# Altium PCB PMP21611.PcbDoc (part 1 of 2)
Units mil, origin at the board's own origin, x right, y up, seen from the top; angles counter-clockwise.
Board outline 4470 x 3145 mil, 4 copper layers (Top Layer, Signal Layer 1, Signal Layer 2, Bottom Layer), stack 60.6 mil thick; 95 components, 31 nets, 221 pads, 370 vias.
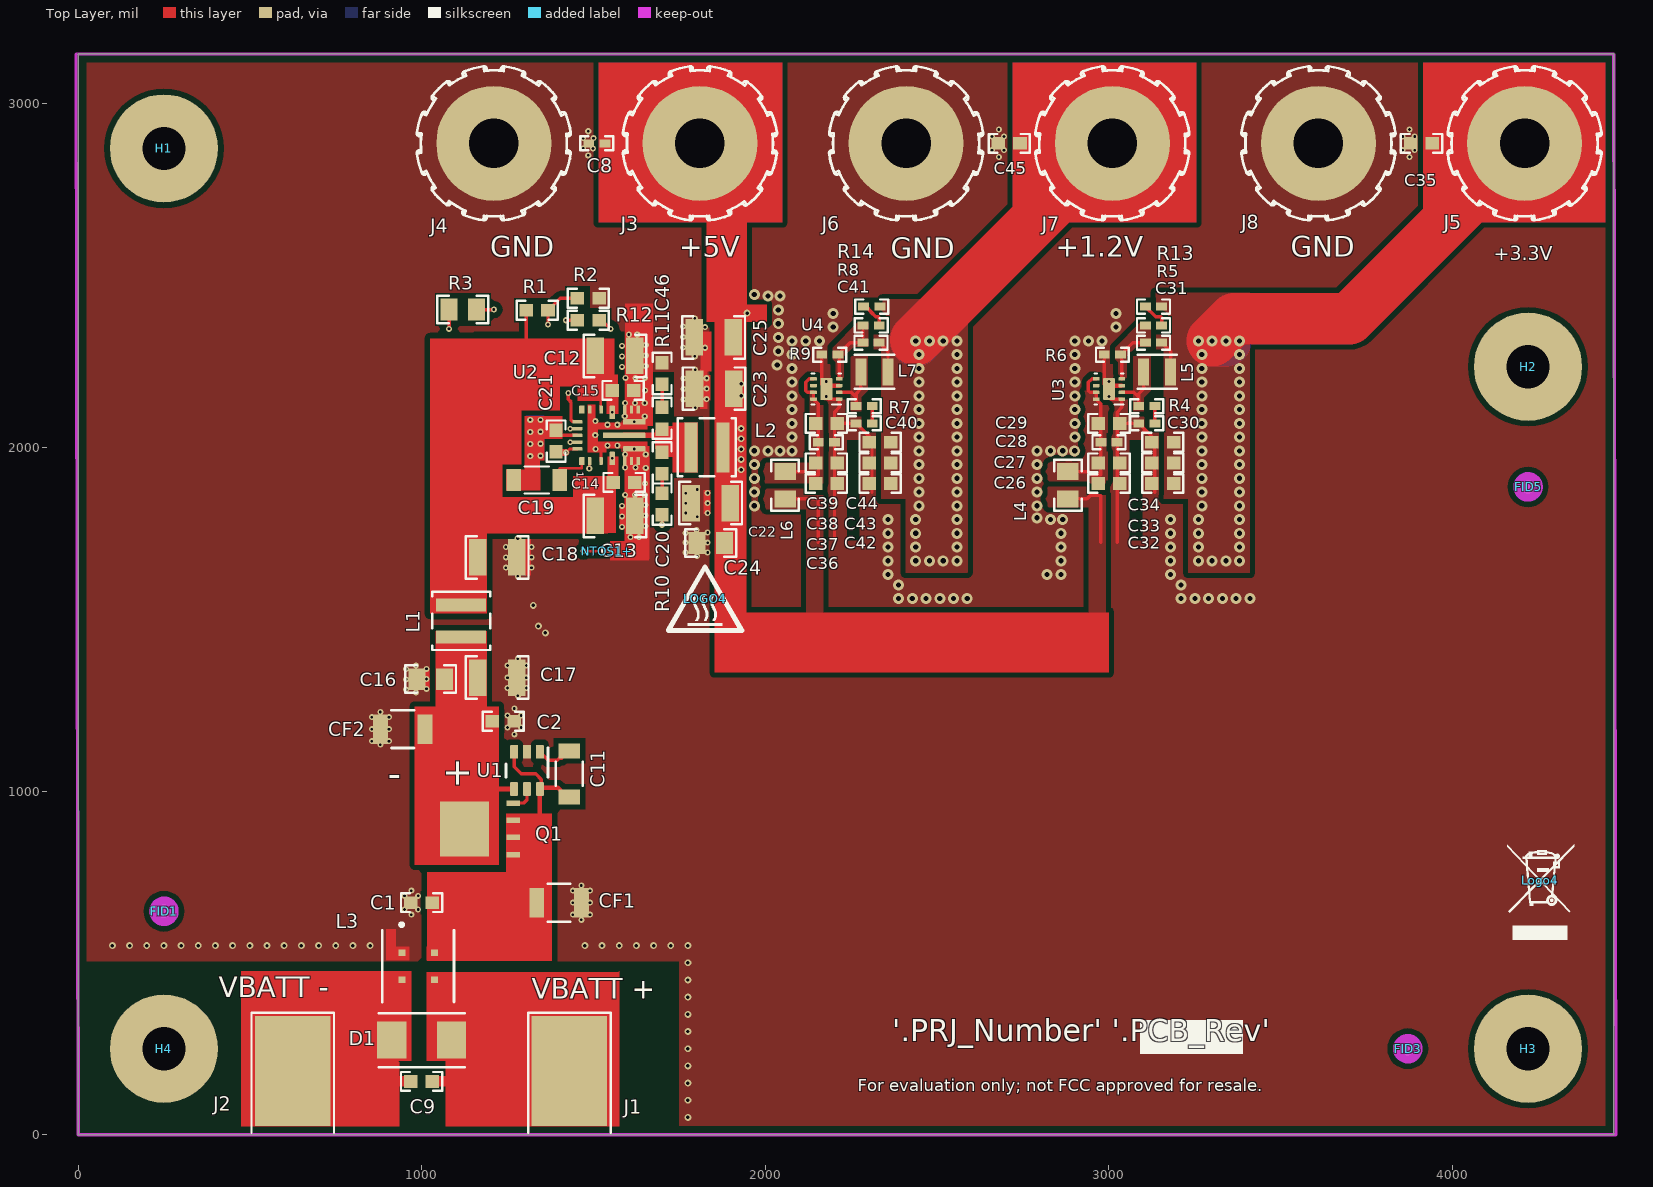
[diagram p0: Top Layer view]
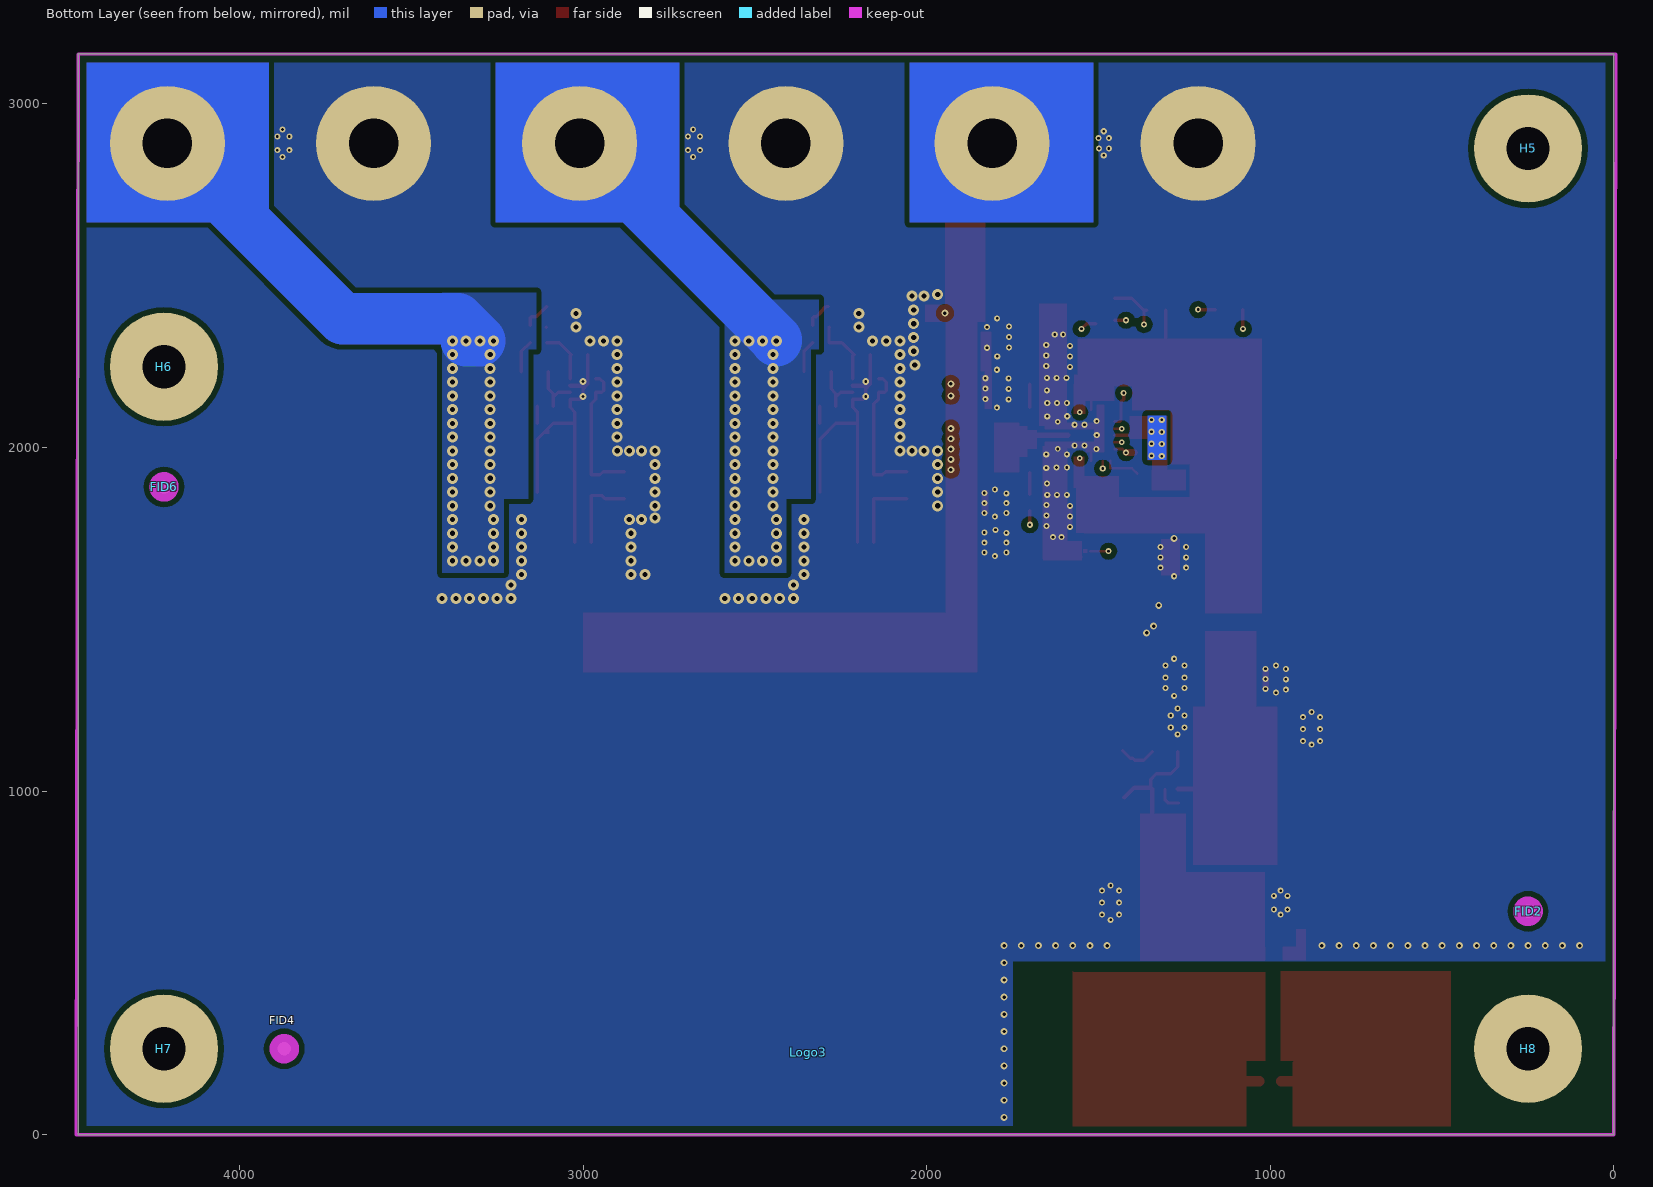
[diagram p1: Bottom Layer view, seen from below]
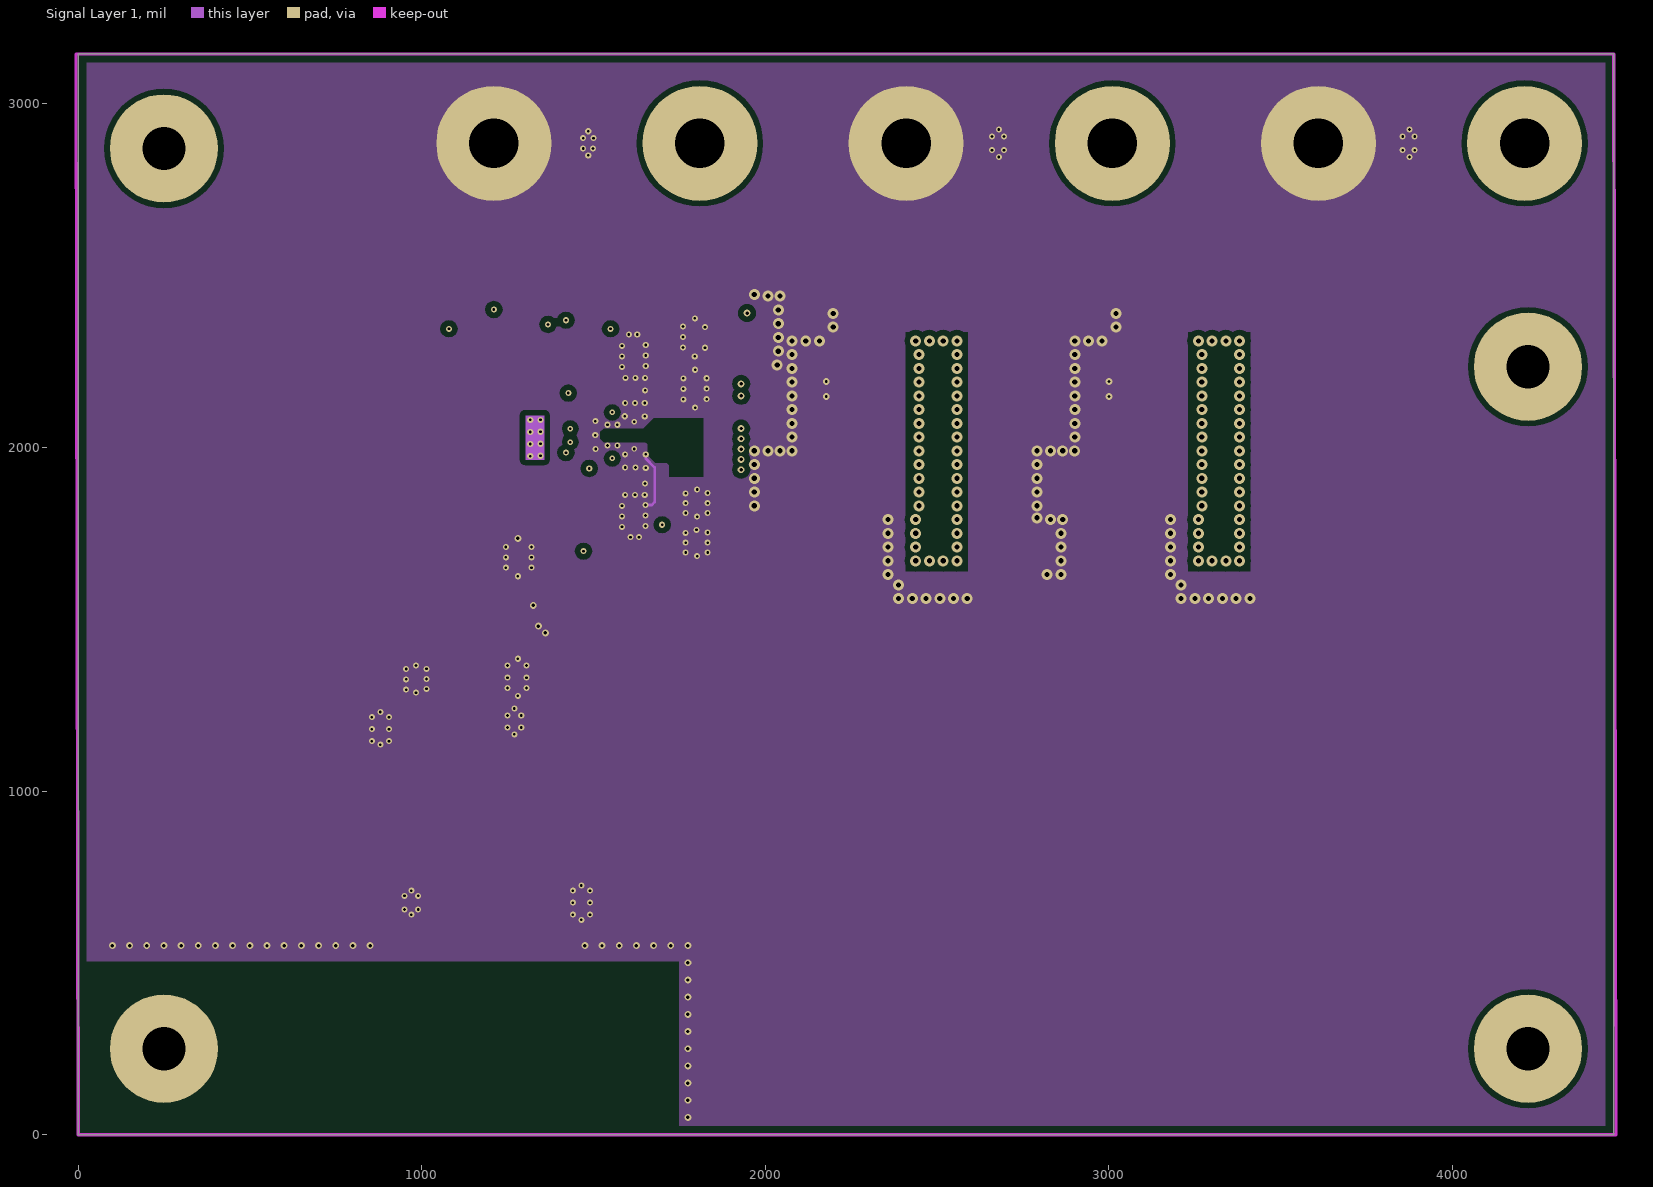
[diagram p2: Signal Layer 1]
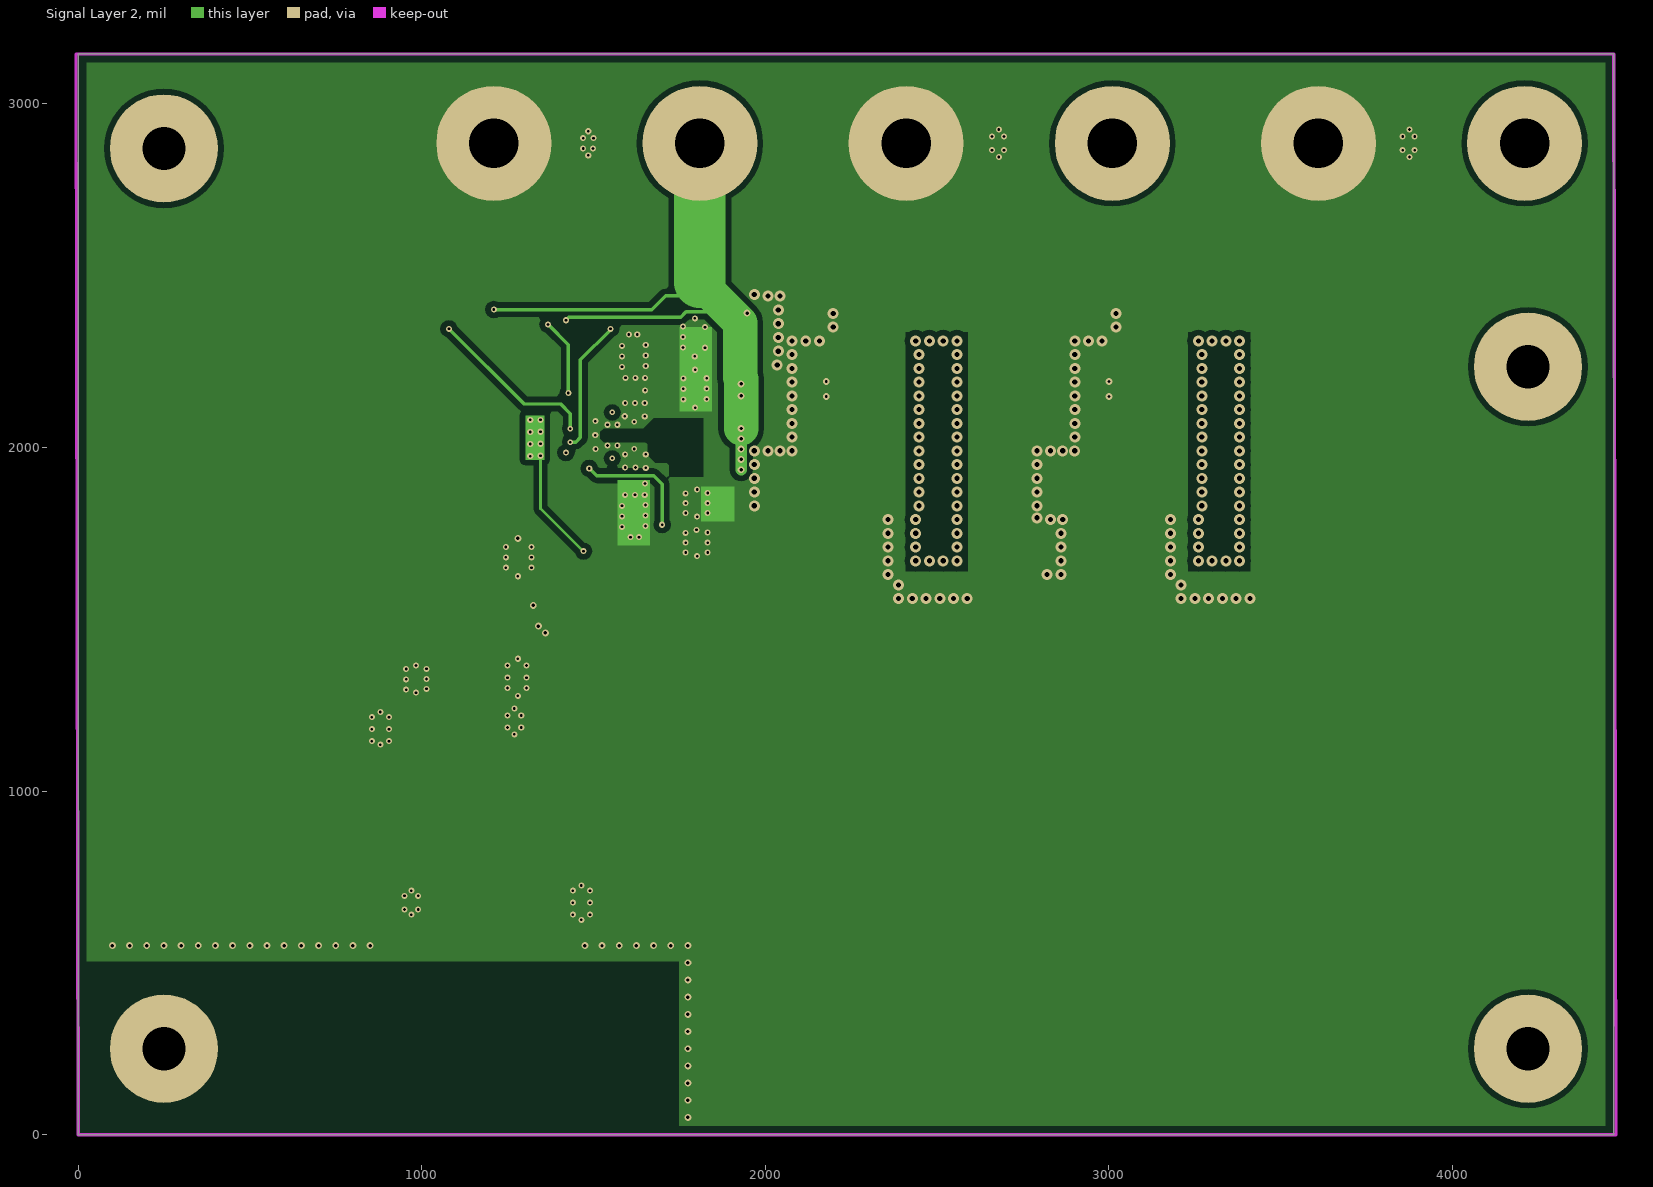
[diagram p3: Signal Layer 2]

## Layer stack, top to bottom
Top Solder: solder mask 0.4, Solder Resist, Dk 3.5
Top Layer: signal copper 1.4
Dielectric 1: prepreg 12, FR-4, Dk 4.2
Signal Layer 1: signal copper 1.4
Dielectric 2: core 31, FR-4, Dk 4.2
Signal Layer 2: signal copper 1.4
Dielectric 3: prepreg 12, FR-4, Dk 4.2
Bottom Layer: signal copper 1.4
Bottom Solder: solder mask 0.4, Solder Resist, Dk 3.5

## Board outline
0,0 0,3145 4470,3145 4470,0

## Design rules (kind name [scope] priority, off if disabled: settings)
AcuteAngle [All] p1: minimum=4.50000000000000E+0001 checktracksonly=FALSE
AssemblyTestPointUsage [All] p1: valid=2
BoardOutlineClearance BoardOutlineClearance_MountingHoles [OnCopper and InComponentClass('Mounting Holes')] p1: gap=40 ignorepadtopadclearanceinfootprint=FALSE
BoardOutlineClearance BoardOutlineClearance_Poly [OnCopper and IsPoly] p2: gap=25 ignorepadtopadclearanceinfootprint=FALSE
BoardOutlineClearance [OnCopper and Not InComponentClass('Logo') and not InComponentClass('FiducialMark') and not InRegion(1000,500,4000,800) and not InPoly] p3: gap=25 ignorepadtopadclearanceinfootprint=FALSE
Clearance Clearance_Keepouts [((IsTrack Or IsArc) And Not InPoly) And IsFree and IsKeepOut vs ((IsTrack Or IsArc) And Not InPoly) And IsFree and IsKeepOut] p1: gap=0 ignorepadtopadclearanceinfootprint=FALSE
Clearance Clearance_Poly [InPolygon] p2: gap=15.75 ignorepadtopadclearanceinfootprint=FALSE
Clearance [All] p3: gap=5 ignorepadtopadclearanceinfootprint=FALSE except(0: Arc-Hole Track-Hole SMDPad-Hole THPad-Hole Via-Hole Fill-Hole Poly-Hole Region-Hole Text-Hole)
ComponentClearance ComponentClearance_MountingHoles_FiducialMarks [InComponentClass('Mounting Holes') vs InComponentClass('FiducialMark')] p1: gap=50 collisioncheckmode=3 verticalgap=10 showdistances=FALSE
ComponentClearance ComponentClearance_Shunt [InComponentClass('Header') vs InComponentClass('Shunt')] p2: gap=0 collisioncheckmode=3 verticalgap=0 showdistances=FALSE
ComponentClearance ComponentClearance_Logo [InComponentClass('Logo')] p3: gap=50 collisioncheckmode=3 verticalgap=10 showdistances=FALSE
ComponentClearance ComponentClearance_ScrewToNut [(HasFootprint('NY PMS 440 0025 PH')) vs (HasFootprint('Keystone_1902C'))] p4: gap=5 collisioncheckmode=3 verticalgap=10 showdistances=FALSE
ComponentClearance ComponentClearance_MountingHoles [InComponentClass('Mounting Holes')] p5: gap=250 collisioncheckmode=3 verticalgap=100000 showdistances=FALSE
ComponentClearance ComponentClearance_SmallPassives [HasFootprint('0201*') or HasFootprint('0402*') or HasFootprint('0508') or HasFootprint('0603*') or HasFootprint('0612') or HasFootprint('0805*') or HasFootprint('0815*') or HasFootprint('0830*') or HasFootprint('1206*') or HasFootprint('1210*') or HasFootprint('1808*') or HasFootprint('1812*') or HasFootprint('1825*') or HasFootprint('2010*') or HasFootprint('2220*') or HasFootprint('2225*') or HasFootprint('2512*') or HasFootprint('2728*') or HasFootprint('3518*') vs HasFootprint('0201*') or HasFootprint('0402*') or HasFootprint('0508') or HasFootprint('0603*') or HasFootprint('0612') or HasFootprint('0805*') or HasFootprint('0815*') or HasFootprint('0830*') or HasFootprint('1206*') or HasFootprint('1210*') or HasFootprint('1808*') or HasFootprint('1812*') or HasFootprint('1825*') or HasFootprint('2010*') or HasFootprint('2220*') or HasFootprint('2225*') or HasFootprint('2512*') or HasFootprint('2728*') or HasFootprint('3518*')] p6: gap=14.96 collisioncheckmode=3 verticalgap=10 showdistances=FALSE
ComponentClearance ComponentClearance_THtoSMT [IsThruComponent vs IsSMTComponent] p7: gap=40 collisioncheckmode=3 verticalgap=30 showdistances=FALSE
ComponentClearance ComponentClearance_THtoTH [IsThruComponent vs IsThruComponent] p8: gap=30 collisioncheckmode=3 verticalgap=30 showdistances=FALSE
ComponentClearance [InComponent('No Component') vs InComponent('No Component')] p9: gap=10 collisioncheckmode=3 verticalgap=10 showdistances=FALSE
DiffPairsRouting [All] p1: maxlimit=100 minlimit=10 mostfreqgap=10 toplayer_minwidth=15 toplayer_maxwidth=15 toplayer_prefwidth=15 midlayer1_minwidth=15 midlayer1_maxwidth=15 midlayer1_prefwidth=15 midlayer2_minwidth=15 midlayer2_maxwidth=15 midlayer2_prefwidth=15 bottomlayer_minwidth=15 bottomlayer_maxwidth=15 bottomlayer_prefwidth=15 maxuncoupledlength=1000
FabricationTestPointUsage TestPointUsage [All] p1: valid=2 allowmultiple=FALSE
FabricationTestpoint Testpoint [All] p1: side=3 testpointundercomponent=TRUE minsize=40 maxsize=100 preferedsize=60 minholesize=0 maxholesize=40 preferedholesize=32 testpointgrid=1 allowsidetop=TRUE allowsidebottom=TRUE usegrid=TRUE gridtolerance=0.01
FanoutControl Fanout_LCC [IsLCC] p1: bgadir=Out bgaviamode=Centered fanoutstyle=Auto fanoutdirection=Alternating viagrid=1 // Fanout_LCC (Default Rule)
FanoutControl Fanout_BGA [IsBGA] p2: bgadir=Out bgaviamode=Centered fanoutstyle=Auto fanoutdirection=Alternating viagrid=1 // Fanout_BGA (Default Rule)
FanoutControl Fanout_Default [All] p4: bgadir=Out bgaviamode=Centered fanoutstyle=Auto fanoutdirection=Alternating viagrid=1 // Fanout_Default (Default Rule)
FanoutControl Fanout_Small [(CompPinCount < 5)] p5: bgadir=Out bgaviamode=Centered fanoutstyle=Auto fanoutdirection=OutThenIn viagrid=1 // Fanout_Small (Default Rule)
Height [All] p1: minheight=0 maxheight=2000 prefheight=500
HoleSize [All] p1: absolutevalues=TRUE maxlimit=251 minlimit=7.87 maxpercent=80.000 minpercent=20.000
MinimumAnnularRing MinimumAnnularRing_ThermalPadVias [IsVia and InAnyComponent] p1: minimumring=3.94
MinimumAnnularRing [All] p2: minimumring=3.94
MinimumSolderMaskSliver MinimumSolderMaskSliver_Logo [InComponentClass('Logo') vs InComponentClass('Logo')] p1: minsoldermaskwidth=0.7
MinimumSolderMaskSliver [All] p2: minsoldermaskwidth=3.94
PlaneConnect [All] p1: planeconnectstyle=Relief reliefexpansion=10 reliefentries=4 reliefconductorwidth=10 reliefairgap=10
PolygonConnect [All] p1: connectstyle=Direct reliefconductorwidth=10 reliefentries=4 polygonreliefangle="90 Angle" airgapwidth=10
RoutingVias ThermalPadVias [IsVia and InAnyComponent] p1: holewidth=7.87 width=19.68 viastyle="Through Hole" minholewidth=7.87 minwidth=15.75 maxholewidth=12.99 maxwidth=23.62
RoutingVias [All] p2: holewidth=16 width=34 viastyle="Through Hole" minholewidth=7.87 minwidth=15.75 maxholewidth=40 maxwidth=65
SilkToBoardRegionClearance [Not ((IsComment or IsDesignator) And (Hide <> 'False')) and not InRegion(1000,500,4000,800)] p1:
SilkToSilkClearance SilkToSilkClearance_Pb-FreeLogo [(HasFootprint('Pb-Free_Overlay_Medium') OR HasFootprint('Pb-Free_Overlay_Small')) vs (HasFootprint('Pb-Free_Overlay_Medium') OR HasFootprint('Pb-Free_Overlay_Small'))] p1: silktosilkclearance=0
SilkToSilkClearance [All] p2: silktosilkclearance=4
SilkToSolderMaskClearance SilkToComponentPadClearance [(IsPad or IsFill or IsRegion) and InAnycomponent] p1: minsilkscreentomaskgap=5 clearancetoexposedcopper=TRUE
SilkToSolderMaskClearance "Silk to Solder Mask Opening" [All] p2: minsilkscreentomaskgap=4 clearancetoexposedcopper=FALSE
SolderMaskExpansion [All] p1: expansion=1.97
Width [All] p1: maxlimit=200 minlimit=6 preferedwidth=10 checkconnectedcopper=TRUE
14 further rules are at their usual default settings.

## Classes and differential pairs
component class PMP21611_Dual: C26 C27 C28 C29 C30 C31 C32 C33 C34 C35 C36 C37 C38 C39 C40 C41 C42 C43 C44 C45 C48 C49 C50 C59 C60 J5 J6 J7 J8 L4 L5 L6 L7 R4 R5 R6 R7 R8 R9 R13 R14 U3 U4
component class PMP21611_Main: C1 C2 C8 C9 C11 C12 C13 C14 C15 C16 C17 C18 C19 C20 C21 C22 C23 C24 C25 C46 CF1 CF2 D1 J1 J2 J3 J4 L1 L2 L3 LOGO4 NTOS1+ Q1 R1 R2 R3 R10 R11 R12 R_FB1 U1 U2
component class PMP21611_Hardware: !PCB1 FID1 FID2 FID3 FID4 FID5 FID6 H1 H2 H3 H4 H5 H6 H7 H8 Logo3 Logo4

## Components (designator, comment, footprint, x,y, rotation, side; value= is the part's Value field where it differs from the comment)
C1 "CMP-0007135-4" 0603 1000,675 r180 top value=0.1uF
C2 "CMP-0007135-4" 0603 1237.69,1203 r0 top value=0.1uF
C8 "GCM155R71A104KA55D" 0402 1510,2885 r180 top value=0.1uF
C9 "06031C472KAT2A" 0603 1000,155 r180 top value=4700pF
C11 "C3216X7R1H225K160AB" 1206_180 1430,1050 r90 top value=2.2uF
C12 "GRM32ER7YA106KA12K" 1210_270 1562.72,2266.3 r0 top value=10uF
C13 "GRM32ER7YA106KA12K" 1210_270 1562.72,1800.75 r0 top value=10uF
C14 "C1608X7R1H473K080AA" 0603 1589.25,1898.19 r0 top value=0.047uF
C15 "C1608X7R1H473K080AA" 0603 1586.34,2165.91 r0 top value=0.047uF
C16 "C0805C104K5RACTU" 0805_HV 1026.19,1325.75 r180 top value=0.1uF
C17 "CL32B106KBJNNWE" 1210_270 1220,1330 r0 top value=10uF
C18 "CL32B106KBJNNWE" 1210_270 1220,1680 r0 top value=10uF
C19 "C3216X7R1H225K160AB" 1206_180 1335,1905 r180 top value=2.2uF
C20 "GCM188R71C474KA55D" 0603 1700,1955 r270 top locked value=0.47uF
C21 "GRM188R71H104KA93D" 0603 1391.46,2018.27 r270 top value=0.1uF
C22 "GRM32ER71A226ME20L" 1210_270 1841.16,1837.82 r180 top value=22uF
C23 "GRM32ER71A226ME20L" 1210_270 1851.14,2170.83 r180 top value=22uF
C24 "08055C473JAT2A" 0805_HV 1841.16,1721.8 r180 top value=0.047uF
C25 "GRM32ER71A226ME20L" 1210_270 1850,2320 r180 top value=22uF
C26 "GRM188Z71A106MA73D" 0603 3000.55,1895 r0 top value=10uF
C27 "GRM188Z71A106MA73D" 0603 3000.55,1955 r0 top value=10uF
C28 "GRM155R71A473KA01D" 0402 3000.55,2015 r0 top value=0.047uF
C29 "UMK107AB7105KA-T" 0603 3000.55,2070 r0 top value=1uF
C30 "GRM155R71H821KA01D" 0402 3110.55,2070 r180 top value=820pF
C31 "885012005055" 0402 3130,2305 r180 top value=10pF
C32 "GRM188Z71A106MA73D" 0603 3156.93,1895 r180 top value=10uF
C33 "GRM188Z71A106MA73D" 0603 3156.93,1955 r180 top value=10uF
C34 "UMK107AB7105KA-T" 0603 3156.93,2015 r180 top value=1uF
C35 "GCM188R71C474KA55D" 0603 3910,2885 r180 top value=0.47uF
C36 "GRM188Z71A106MA73D" 0603 2177.95,1895 r0 top value=10uF
C37 "GRM188Z71A106MA73D" 0603 2177.95,1955 r0 top value=10uF
C38 "GRM155R71A473KA01D" 0402 2177.95,2015 r0 top value=0.047uF
C39 "UMK107AB7105KA-T" 0603 2177.95,2070 r0 top value=1uF
C40 "GRM155R71H821KA01D" 0402 2287.95,2070 r180 top value=820pF
C41 "885012005043" 0402 2307.95,2305 r180 top value=33pF
C42 "GRM188Z71A106MA73D" 0603 2334.33,1895 r180 top value=10uF
C43 "GRM188Z71A106MA73D" 0603 2334.33,1955 r180 top value=10uF
C44 "UMK107AB7105KA-T" 0603 2334.33,2015 r180 top value=1uF
C45 "GCM188R71C474KA55D" 0603 2710,2885 r180 top value=0.47uF
C46 "C0603C821K5RACTU" 0603 1700,2215 r90 top value=820pF
CF1 "CMP-0009163-2" 1210_280 1400,675 r0 top value=4.7uF
CF2 "CMP-0009163-2" 1210_280 945,1180 r180 top value=4.7uF
D1 "CMP-0006046-2" SMB-Bi 1000,275 r180 top value=28V
FID1 "Fiducial" Fiducial10-20 250,650 r0 top
FID2 "Fiducial" Fiducial10-20 250,650 r180 bottom
FID3 "Fiducial" Fiducial10-20 3870,250 r0 top
FID4 "Fiducial" Fiducial10-20 3870,250 r180 bottom
FID5 "Fiducial" Fiducial10-20 4220,1885 r0 top
FID6 "Fiducial" Fiducial10-20 4220,1885 r180 bottom
H1 "NY PMS 440 0025 PH" "NY PMS 440 0025 PH" 250,2870 r0 top
H2 "NY PMS 440 0025 PH" "NY PMS 440 0025 PH" 4220,2235 r0 top
H3 "NY PMS 440 0025 PH" "NY PMS 440 0025 PH" 4220,250 r0 top
H4 "NY PMS 440 0025 PH" "NY PMS 440 0025 PH" 250,250 r0 top
H5 "1902B" Keystone_1902B 250,2870 r180 bottom
H6 "1902B" Keystone_1902B 4220,2235 r180 bottom
H7 "1902B" Keystone_1902B 4220,250 r180 bottom
H8 "1902B" Keystone_1902B 250,250 r180 bottom
J1 "VBATT +" 6091 1430,0 r90 top
J2 "VBATT -" 6092 625,0 r90 top
J3 "111-0702-001" Emerson_111-0702-001 1810,2885 r0 top
J4 "111-0703-001" Emerson_111-0703-001 1210,2885 r0 top
J5 "111-0702-001" Emerson_111-0702-001 4210,2885 r0 top
J6 "111-0703-001" Emerson_111-0703-001 2410,2885 r0 top
J7 "111-0702-001" Emerson_111-0702-001 3010,2885 r0 top
J8 "111-0703-001" Emerson_111-0703-001 3610,2885 r0 top
L1 "CMP-0060986-1" XAL4020 1115,1495 r90 top value=2.2uH
L2 "CMP-0060986-1" XAL4020 1830,2000 r0 top value=2.2uH
L3 "CMP-0076877-1" DLW5BT_TQ2 990,490 r0 top
L4 "7427920415" 0805_HV 2880.71,1890.16 r90 top value="600 ohm"
L5 "CMP-0058895-1" DFE252012C 3140.55,2220 r0 top value=1uH
L6 "7427920415" 0805_HV 2058.11,1890.16 r90 top value="600 ohm"
L7 "CMP-0058895-1" DFE252012C 2317.95,2220 r0 top value=1uH
Logo3 "FCC disclaimer" FCC_disclaimer 2345,240 r90 bottom
Logo4 "WEEE logo" WEEE_Minimum 4255,740 r0 top
LOGO4 "CAUTION HOT SURFACE" IEC_HotSurface_Small 1825,1560 r0 top
NTOS1+ "CMP-0078142-2" Net-Tie_10mil 1539,1698 r0 top net-tie
Q1 "CMP-0000747-1" PowerPAK_SO-8L 1156.69,890 r180 top value=40V
R1 "CRCW0603100KFKEA" 0603 1336.34,2399.17 r180 top value=100k
R2 "CRCW0603100KFKEA" 0603 1484.96,2434.17 r180 top value=100k
R3 "CRCW0805100KFKEA" 0805_HV 1119.8,2401.14 r0 top value=100k
R4 "CMP-0026565-2" 0402 3110.55,2120 r180 top value=7.50
R5 "CRCW0402806KFKED" 0402 3130,2355 r0 top value=806k
R6 "RC0402FR-07180KL" 0402 3010.55,2270 r0 top value=180k
R7 "CMP-0026565-2" 0402 2287.95,2120 r180 top value=7.50
R8 "RC0402FR-07180KL" 0402 2308.11,2355 r0 top value=180k
R9 "RC0402FR-07180KL" 0402 2187.95,2270 r0 top value=180k
R10 "RMCF0603ZT0R00" 0603 1700,1835 r90 top value=0
R11 "CRCW06037R50JNEA" 0603 1700,2085 r90 top value=7.5
R12 "RMCF0603ZT0R00" 0603 1485,2370 r180 top value=0
R13 "CRCW040247R5FKED" 0402 3130,2410 r0 top value=47.5
R14 "CRCW040247R5FKED" 0402 2310,2410 r0 top value=47.5
U1 "LM74700QDBVTQ1" DBV0006A_N 1306.69,1060 r270 top
U2 "LM53635LQRNLRQ1" RNL0022A 1545,2035 r90 top locked
U3 "TPS62067QDSGRQ1" DSG0008A 3000.55,2170 r180 top
U4 "TPS62067QDSGRQ1" DSG0008A 2177.95,2170 r180 top

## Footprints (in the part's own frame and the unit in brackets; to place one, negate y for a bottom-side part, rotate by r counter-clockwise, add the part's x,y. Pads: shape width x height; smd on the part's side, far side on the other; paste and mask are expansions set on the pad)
0402 [mm] "0402 from SM-752 data"
  rect 0.8x0.6 smd: 1(-0.6,0) 2(0.6,0)
  silkscreen extent -1.22,-0.52 1.22,0.52, body extent -0.55,-0.3 0.55,0.3, height 0.6
0603 [mm] "0603 from SM-752 data"
  rect 1x0.95 smd: 1(-0.8,0) 2(0.8,0)
  silkscreen extent -1.52,-0.69 1.52,0.69, body extent -0.87,-0.47 0.87,0.47, height 1
0805_HV [mil] "0805 with 30mil clearance between pads"
  rect 50x63 smd: 1(-40,0) 2(40,0)
  silkscreen extent -74,-40 74,40, body extent -43,-29 43,29, height 57
1206_180 [mm] "1206_180"
  rect 1.1x1.6 smd: 1(-1.7,0) 2(1.7,0)
  silkscreen extent -0.9,-1 0.9,1, body extent -1.75,-0.95 1.75,0.95, height 1.8
1210_270 [mm] "1210"
  rect 1.3x2.7 smd: 1(-1.45,0) 2(1.45,0)
  silkscreen extent -2.32,-1.57 2.32,1.57, body extent -1.7,-1.35 1.7,1.35, height 2.7
1210_280 [mm] "SMD, 2-Leads, Body 3.6x2.8mm, Height 2.8mm"
  rect 1.1x2.2 smd: 1(-1.65,0) 2(1.65,0)
  silkscreen extent -0.84,-1.4 0.84,1.4, body extent -1.8,-1.4 1.8,1.4, height 2.8
6091 [mil] "Keystone Insulated End Launch Banana Jack"
  rect 320x220 smd: 1(185,0)
  silkscreen extent 5,-120 355,120, body extent -666,-216 271,216, height 227
6092 [mil] "Keystone Insulated End Launch Banana Jack"
  rect 320x220 smd: 1(185,0)
  silkscreen extent 5,-120 355,120, body extent -666,-216 271,216, height 227
DBV0006A_N [mm] "SOT23, 6-Leads, Body 2.9x1.6mm, Pitch 0.95mm, Lead Span 2.8mm, IPC Medium Density"
  rrect17% 1x0.6 smd: 1(-1.375,0.95) 2(-1.375,0) 3(-1.375,-0.95) 4(1.375,-0.95) 5(1.375,0) 6(1.375,0.95)
  silkscreen extent -1.68,-1.55 0.5,1.55, body extent -1.42,-1.46 1.42,1.46, height 1.12
DFE252012C [mm] "Toko"
  rect 0.8x2 smd: 1(-1,0) 2(1,0)
  silkscreen extent -1.45,-1.25 1.45,1.25, body extent -1.35,-1.1 1.35,1.1, height 1.2
DLW5BT_TQ2 [mm] "SMD, 4-Leads, Body 5x5mm"
  rect 0.5x0.5 smd: 1(-1.2,1) 2(-1.2,-1) 3(1.2,-1) 4(1.2,1)
  Top Layer region: -2.35,-0.45 -0.65,-0.45 -0.65,-1.45 -1.65,-1.45 -1.65,-2.75 -2.35,-2.75
  Top Layer region: -2.35,0.45 -0.65,0.45 -0.65,1.45 -1.65,1.45 -1.65,2.75 -2.35,2.75
  Top Layer region: 2.35,-0.45 0.65,-0.45 0.65,-1.45 1.65,-1.45 1.65,-2.75 2.35,-2.75
  Top Layer region: 2.35,0.45 0.65,0.45 0.65,1.45 1.65,1.45 1.65,2.75 2.35,2.75
  silkscreen extent -2.65,-2.65 2.65,3.2, body extent -2.65,-2.65 2.65,2.65, height 2.51
DSG0008A [mm] "SON, 8-Leads, Body 2x2mm, Pitch 0.5mm, Thermal Pad 1.6x0.9mm, TI Recommended"
  rrect40% 0.5x0.25 smd: 1(-0.95,0.75) 2(-0.95,0.25) 3(-0.95,-0.25) 4(-0.95,-0.75) 5(0.95,-0.75) 6(0.95,-0.25) 7(0.95,0.25) 8(0.95,0.75)
  rrect14% 0.9x0.7 on Top Paste: 9(0,0.45) 9(0,-0.45)
  rrect11% 0.9x1.6 smd paste-0.45: 9(0,0)
  silkscreen extent -1.07,-1.15 1.07,1.15, body extent -1,-1 1,1, height 0.77
Emerson_111-0702-001 [mm] "Receptacle, 1x1 Position, Dia 10.74mm, Red, TH"
  round 8.5 hole 3.658: 1(0,0)
  silkscreen extent -5.69,-5.69 5.69,5.69, body extent -5.69,-5.69 5.69,5.69, height 26.47
Emerson_111-0703-001 [mm] "Receptacle, 1x1 Position, Dia 10.74mm, Black, TH"
  round 8.5 hole 3.658: 1(0,0)
  silkscreen extent -5.69,-5.69 5.69,5.69, body extent -5.69,-5.69 5.69,5.69, height 26.48
FCC_disclaimer [mil]
Fiducial10-20 [mm]
  round 1 smd mask+0.5: 1(0,0)
  Top Layer keep-out circle w1.178: c0,0 r0.5
IEC_HotSurface_Small [mil]
  silkscreen extent -107,-93 107,92
Keystone_1902B [mil] "Hex Standoff, 4-40 threaded, nylon"
  round 1 on Mech4: 0(0,0)
  body extent -145,-126 145,126, height 375
Net-Tie_10mil [mil] "10mil net tie, no solder mask opening, no solder paste"
  rect 10x10 smd paste-5 mask-5: 1(-10,0) 2(10,0)
  Top Layer region: -6,5 6,5 6,-5 -6,-5
"NY PMS 440 0025 PH" [mm] "4-40 nylon screw and mounting hole"
  round 8 hole 3.2: 1(0,0)
  body extent -3.3,-3.3 3.3,3.3, height 2.69
PowerPAK_SO-8L [mm] "based on Vishay recommended land pattern Document 63818 Feb 7, 2012"
  rect 1x0.41 smd: 1(-2.805,1.905) 2(-2.805,0.635) 3(-2.805,-0.635) 4(-2.805,-1.905)
  rect 3.63x4.061 smd: 5(0.805,0)
  Top Layer region: 2.615,-2.5 3.125,-2.5 3.125,2.5 2.615,2.5
  Top Layer region: -0.298,2.03 0.298,2.03 0.298,2.64 -0.298,2.64
  Top Layer region: -0.298,-2.64 0.298,-2.64 0.298,-2.03 -0.298,-2.03
  body extent -3.07,-2.57 3.08,2.57, height 1.21
RNL0022A [mm] "VQFN-HR-22"
  rrect25% 0.6x0.4 smd: 1(-1.9,2) 17(1.9,2)
  rrect40% 0.6x0.25 smd: 2(-1.9,1.425) 3(-1.9,0.575) 5(-1.9,-1.175) 6(-1.9,-1.675) 7(-1.9,-2.175) 11(1.9,-2.175) 12(1.9,-1.675) 13(1.9,-1.175) 15(1.9,0.575) 16(1.9,1.425)
  rrect25% 1x0.4 smd paste-0.25: 4(-1.7,-0.25) 14(1.7,-0.25)
  rrect25% 0.4x0.4 on Top Paste: 4A(-2,-0.25) 4B(-1.4,-0.25) 14A(1.4,-0.25) 14B(2,-0.25)
  rrect25% 0.4x1.65 smd paste-0.25: 8(-1,-1.875) 10(1,-1.875)
  rrect25% 0.4x0.66 on Top Paste: 8A(-1,-1.445) 8B(-1,-2.305) 10A(1,-1.445) 10B(1,-2.305)
  rrect25% 0.4x3.15 smd paste-0.25: 9(0,-1.125)
  rrect25% 0.4x0.63 on Top Paste: 9A(0,0.12) 9B(0,-0.71) 9C(0,-1.54) 9D(0,-2.37)
  rrect40% 0.25x0.75 smd: 18(1,2.325) 19(0.5,2.325) 20(0,2.325) 21(-0.5,2.325) 22(-1,2.325)
  body extent -2,-2.5 2,2.5, height 0.9
SMB-Bi [mil] "Molded Diode, 2-Leads, Body 5.4x3.6mm, IPC Medium Density, based on OnSemi component dimensions"
  rect 85x107.99 smd: 1(-87.01,0) 2(87.01,0)
  silkscreen extent -125,-79 125,79, body extent -104,-73 104,73, height 89
WEEE_Minimum [mil] "WEEElie bin"
  silkscreen extent -95,-172 99,104
XAL4020 [mil] "Coilcraft XAL4020 7/18/12"
  rect 38x146 smd: 1(-46.5,0) 2(46.5,0)
  silkscreen extent -84,-84 84,84, body extent -84,-84 84,84, height 83

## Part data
C1 C2: "CAP, CERM, 0.1 uF, 16 V, +/- 10%, X7R, AEC-Q200 Grade 1, 0603", Cap_Case=0603, Manufacturer=MuRata, PartNumber=GCM188R71C104KA37J, Supplier Part Number 1=490-8015-1-ND, TempCo=X7R, Tolerance_%=10%, Value1=Unknown, Value2=16V, ValueDisplayed=0.1uF
C8: library part CMP-0006350-2, "CAP, CERM, 0.1 uF, 10 V, +/- 10%, X7R, AEC-Q200 Grade 1, 0402", Cap_Case=0402, Manufacturer=MuRata, Supplier Part Number 1=81-GCM155R71A104K5D, TempCo=X7R, Tolerance_%=10%, Value1=Unknown, Value2=10V, ValueDisplayed=0.1uF
C9: library part CMP-0006746-5, "CAP, CERM, 4700 pF, 100 V, +/- 10%, X7R, 0603", Cap_Case=0603, Manufacturer=AVX, Supplier Part Number 1=478-1203-1-ND, TempCo=X7R, Tolerance_%=10%, Value1="0.136 ohm", Value2=100V, ValueDisplayed=4700pF
C11 C19: library part CMP-0008698-2, "CAP, CERM, 2.2 uF, 50 V, +/- 10%, X7R, 1206", Cap_Case=1206_180, Manufacturer=TDK, Supplier Part Number 1=445-7697-1-ND, TempCo=X7R, Tolerance_%=10%, Value1="0.005887 ohm", Value2=50V, ValueDisplayed=2.2uF
C12 C13: library part CMP-0081639-1, "CAP, CERM, 10 µF, 35 V,+/- 10%, X7R, 1210", Cap_Case=1210, Manufacturer=MuRata, Supplier Part Number 1=GRM32ER7YA106KA12K-ND, TempCo=X7R, Tolerance_%=10%, Value1="0.001 ohm", Value2=35V, ValueDisplayed=10µF
C14 C15: library part CMP-0007049-4, "CAP, CERM, 0.047 uF, 50 V, +/- 10%, X7R, 0603", Cap_Case=0603, Manufacturer=TDK, Supplier Part Number 1=445-1313-1-ND, TempCo=X7R, Tolerance_%=10%, Value1="0.049007 ohm", Value2=50V, ValueDisplayed=0.047uF
C16: library part CMP-0007726-2, "CAP, CERM, 0.1 uF, 50 V, +/- 10%, X7R, 0805", Cap_Case=0805, Manufacturer=Kemet, Supplier Part Number 1=399-1170-1-ND, TempCo=X7R, Tolerance_%=10%, Value1="0.064 ohm", Value2=50V, ValueDisplayed=0.1uF
C17 C18: library part CMP-0079201-1, "CAP, CERM, 10 µF, 50 V,+/- 10%, X7R, 1210", Cap_Case=1210, Manufacturer="Samsung Electro-Mechanics", Supplier Part Number 1=1276-3388-1-ND, TempCo=X7R, Tolerance_%=10%, Value1="0.005 ohm", Value2=50V, ValueDisplayed=10µF
C20 C35 C45: library part CMP-0007138-4, "CAP, CERM, 0.47 uF, 16 V, +/- 10%, X7R, AEC-Q200 Grade 1, 0603", Cap_Case=0603, Manufacturer=MuRata, Supplier Part Number 1=490-4775-1-ND, TempCo=X7R, Tolerance_%=10%, Value1=Unknown, Value2=16V, ValueDisplayed=0.47uF
C21: library part CMP-0007434-4, "CAP, CERM, 0.1 uF, 50 V, +/- 10%, X7R, 0603", Cap_Case=0603, Manufacturer=MuRata, Supplier Part Number 1=490-1519-1-ND, TempCo=X7R, Tolerance_%=10%, Value1=Unknown, Value2=50V, ValueDisplayed=0.1uF
C22 C23 C25: library part CMP-0009219-2, "CAP, CERM, 22 uF, 10 V, +/- 10%, X7R, 1210", Cap_Case=1210, Manufacturer=MuRata, Supplier Part Number 1=490-11653-1-ND, TempCo=X7R, Tolerance_%=10%, Value1="0.002 ohm", Value2=10V, ValueDisplayed=22uF
C24: library part CMP-0007658-2, "CAP, CERM, 0.047 uF, 50 V, +/- 5%, X7R, 0805", Cap_Case=0805, Manufacturer=AVX, Supplier Part Number 1=478-3771-1-ND, TempCo=X7R, Tolerance_%=5%, Value1="0.035 ohm", Value2=50V, ValueDisplayed=0.047uF
C26 C27 C32 C33 C36 C37 C42 C43: library part CMP-0007497-5, "CAP, CERM, 10 uF, 10 V, +/- 20%, X7R, 0603", Cap_Case=0603, Manufacturer=MuRata, Supplier Part Number 1=81-GRM188Z71A106MA3D, TempCo=X7R, Tolerance_%=20%, Value1=Unknown, Value2=10V, ValueDisplayed=10uF
C28 C38: library part CMP-0006634-2, "CAP, CERM, 0.047 uF, 10 V, +/- 10%, X7R, 0402", Cap_Case=0402, Manufacturer=MuRata, Supplier Part Number 1=490-1316-1-ND, TempCo=X7R, Tolerance_%=10%, Value1=Unknown, Value2=10V, ValueDisplayed=0.047uF
C29 C34 C39 C44: library part CMP-0007508-5, "CAP, CERM, 1 uF, 50 V, +/- 10%, X7R, 0603", Cap_Case=0603, Manufacturer="Taiyo Yuden", Supplier Part Number 1=587-3247-1-ND, TempCo=X7R, Tolerance_%=10%, Value1=Unknown, Value2=50V, ValueDisplayed=1uF
C30 C40: library part CMP-0006697-2, "CAP, CERM, 820 pF, 50 V, +/- 10%, X7R, 0402", Cap_Case=0402, Manufacturer=MuRata, Supplier Part Number 1=490-3250-1-ND, TempCo=X7R, Tolerance_%=10%, Value1=Unknown, Value2=50V, ValueDisplayed=820pF
C31: library part CMP-0006215-2, "CAP, CERM, 10 pF, 50 V, +/- 5%, C0G/NP0, 0402", Cap_Case=0402, Manufacturer="Wurth Elektronik", Supplier Part Number 1=732-7469-1-ND, TempCo=C0G/NP0, Tolerance_%=5%, Value1=Unknown, Value2=50V, ValueDisplayed=10pF
C41: library part CMP-0006213-2, "CAP, CERM, 33 pF, 25 V, +/- 5%, C0G/NP0, 0402", Cap_Case=0402, Manufacturer="Wurth Elektronik", Supplier Part Number 1=710-885012005043, TempCo=C0G/NP0, Tolerance_%=5%, Value1=Unknown, Value2=25V, ValueDisplayed=33pF
C46: library part CMP-0006972-5, "CAP, CERM, 820 pF, 50 V, +/- 10%, X7R, 0603", Cap_Case=0603, Manufacturer=Kemet, Supplier Part Number 1=399-1078-1-ND, TempCo=X7R, Tolerance_%=10%, Value1=Unknown, Value2=50V, ValueDisplayed=820pF
CF1 CF2: "CAP, CERM, 4.7 uF, 50 V, +/- 20%, X7R, AEC-Q200 Grade 1, 1210", Cap_Case=1210, Manufacturer=TDK, PartNumber=CGA6P3X7R1H475M250AB, Supplier Part Number 1=445-13030-1-ND, TempCo=X7R, Tolerance_%=20%, Value1=Unknown, Value2=50V, ValueDisplayed=4.7uF
D1: "Diode, TVS, Bi, 28 V, 45.4 Vc, SMB", Manufacturer="Diodes Inc.", PartNumber=SMBJ28CA-13-F, Power_W=5W, Supplier Part Number 1=SMBJ28CA-FDICT-ND
FID1 FID2 FID3 FID4 FID5 FID6: "Fiducial mark.  There is nothing to buy or mount.", Manufacturer=N/A
H1 H2 H3 H4: library part CMP-0003617-1, "Machine Screw, Round, #4-40 x 1/4, Nylon, Philips panhead", Manufacturer="B&F Fastener Supply", Supplier Part Number 1=H542-ND
H5 H6 H7 H8: library part CMP-0003658-1, Manufacturer=Keystone, Supplier Part Number 1=36-1902B-ND
J1: library part CMP-0055167-2, "Standard Banana Jack, Insulated, Red", Manufacturer=Keystone, PartNumber=6091, Supplier Part Number 1=36-6091-ND
J2: library part CMP-0055168-2, "Standard Banana Jack, Insulated, Black", Manufacturer=Keystone, PartNumber=6092, Supplier Part Number 1=36-6092-ND
J3 J5 J7: library part CMP-0075036-1, "Binding Post, Red, TH", Manufacturer="Cinch Connectivity", Supplier Part Number 1=J10125-ND
J4 J6 J8: library part CMP-0075035-1, "Binding Post, Black, TH", Manufacturer="Cinch Connectivity", Supplier Part Number 1=J10126-ND
L1 L2: "Inductor, Shielded, Composite, 2.2 uH, 5.5 A, 0.04 ohm, SMD", Manufacturer=Coilcraft, PartNumber=XAL4020-222MEB, Value1="0.04 ohm", Value2=5.5A, ValueDisplayed=2.2uH
L3: "Coupled inductor, 2.5 A, 0.034 ohm, SMD", Manufacturer=MuRata, PartNumber=DLW5BTM102TQ2K, Supplier Part Number 1=490-9291-1-ND
L4 L6: library part CMP-0003086-1, "Ferrite Bead, 600 ohm @ 100 MHz, 0.5 A, 0805", Manufacturer="Wurth Elektronik", Supplier Part Number 1=732-1605-1-ND, Value1="0.3 ohm", Value2=0.5A, ValueDisplayed="600 ohm"
L5 L7: "Inductor, Shielded, Ferrite, 1 uH, 3 A, 0.045 ohm, SMD", Manufacturer="MuRata Toko", PartNumber=1239AS-H-1R0M{}P2, Value1="0.045 ohm", Value2=3A, ValueDisplayed=1uH
Logo3: library part FCC_disclaimer, "FCC_disclaimer"
Logo4: library part CMP-0074769-1
LOGO4: library part IEC_HotSurface, "IEC 61010-1 Hot Surface Warning"
NTOS1+: "Single point connection between nets.", Manufacturer=N/A
Q1: "MOSFET, N-CH, 40 V, 75 A, PowerPAK_SO-8L", Alternate Manufacturer=None, Manufacturer=Vishay-Siliconix, PartNumber=SQJ422EP-T1-GE3, Supplier Part Number 1=SQJ422EP-T1-GE3-ND, Value1=0.004, Value2="67 nC"
R1 R2: library part CMP-0021990-4, "RES, 100 k, 1%, 0.1 W, AEC-Q200 Grade 0, 0603", Manufacturer=Vishay-Dale, Power_W=100mW, Supplier Part Number 1=541-100KHCT-ND, TempCo="100 ppm/C", Tolerance_%=1%, Value2=0.1W, Value_Code=100k
R3: library part CMP-0020834-3, "RES, 100 k, 1%, 0.125 W, AEC-Q200 Grade 0, 0805", Manufacturer=Vishay-Dale, Power_W=125mW, Supplier Part Number 1=541-100KCCT-ND, TempCo="100 ppm/C", Tolerance_%=1%, Value2=0.125W, Value_Code=100k
R4 R7: "RES, 7.50, 1%, 0.063 W, AEC-Q200 Grade 0, 0402", Manufacturer=Vishay-Dale, PartNumber=CRCW04027R50FKED, Power_W=63mW, Supplier Part Number 1=541-7.50LLCT-ND, TempCo="100 ppm/C", Tolerance_%=1%, Value2=0.063W, Value_Code=7R50, ValueDisplayed=7.50
R5: library part CMP-0026568-2, "RES, 806 k, 1%, 0.063 W, AEC-Q200 Grade 0, 0402", Manufacturer=Vishay-Dale, Power_W=63mW, Supplier Part Number 1=541-806KLCT-ND, TempCo="100 ppm/C", Tolerance_%=1%, Value2=0.063W, Value_Code=806k
R6 R8 R9: library part CMP-0026723-1, "RES, 180 k, 1%, 0.063 W, 0402", Manufacturer="Yageo America", Power_W=63mW, Supplier Part Number 1=311-180KLRCT-ND, TempCo="100 ppm/C", Tolerance_%=1%, Value2=0.063W, Value_Code=180k
R10 R12: library part CMP-0023343-3, "RES, 0, 1%, 0.1 W, AEC-Q200 Grade 0, 0603", Manufacturer="Stackpole Electronics Inc", Power_W=100mW, Supplier Part Number 1=RMCF0603ZT0R00CT-ND, TempCo=ppm/C, Tolerance_%=1%, Value2=0.1W, Value_Code=0
R11: library part CMP-0025857-4, "RES, 7.5, 5%, 0.1 W, AEC-Q200 Grade 0, 0603", Manufacturer=Vishay-Dale, Power_W=100mW, Supplier Part Number 1=541-7.5GCT-ND, TempCo="200 ppm/C", Tolerance_%=5%, Value2=0.1W, Value_Code=7R50, ValueDisplayed=7.5
R13 R14: library part CMP-0026396-2, "RES, 47.5, 1%, 0.063 W, AEC-Q200 Grade 0, 0402", Manufacturer=Vishay-Dale, Power_W=63mW, Supplier Part Number 1=541-47.5LCT-ND, TempCo="100 ppm/C", Tolerance_%=1%, Value2=0.063W, Value_Code=47R5, ValueDisplayed=47.5
U1: library part CMP-0079180-1, "Low Iq Always ON Smart Diode Controller, DBV0006A (SOT-23-6)", Alternate Manufacturer="Texas Instruments", Alternate PartNumber=LM74700QDBVRQ1
U2: library part CMP-0076355-4, "3.5A, 36 V Synchronous, 2.1MHz, Automotive Step Down DC-DC Converter, RNL0022A (VQFN-HR-22)", Alternate Manufacturer="Texas Instruments", Alternate PartNumber=LM53635LQRNLTQ1, Operating Temprature Range="-40 to 150 C", Rating=Automotive
U3 U4: library part CMP-0081411-1, "3MHz, 2A Automotive Step-Down Converter in 2x2 SON Package, DSG0008A (WSON-8)", Alternate Manufacturer="Texas Instruments", Operating Temprature Range="-40 to 125 C", Rating=Automotive

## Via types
v1: diameter 32, hole 15, Top Layer to Bottom Layer, tented both sides, 156 vias
v2: diameter 17.72, hole 7.87, Top Layer to Bottom Layer, tented both sides, 150 vias
v3: diameter 20, hole 10, Top Layer to Bottom Layer, tented both sides, 45 vias
v4: diameter 17.72, hole 7.87, Top Layer to Bottom Layer, 9 vias
v5: diameter 15.75, hole 7.87, Top Layer to Bottom Layer, 5 vias
v6: diameter 19.68, hole 7.87, Top Layer to Bottom Layer, 4 vias
v7: diameter 15.75, hole 7.87, Top Layer to Bottom Layer, tented both sides, 1 vias

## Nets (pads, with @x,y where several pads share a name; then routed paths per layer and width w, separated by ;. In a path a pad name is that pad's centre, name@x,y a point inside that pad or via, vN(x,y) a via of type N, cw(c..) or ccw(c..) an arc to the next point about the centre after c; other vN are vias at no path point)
+1.2V: C41.1 C42.1 C43.1 C44.1 C45.1 J7.1 L7.2 R14.2 | length 1988.3
  Top Layer w10: C41.1@2331.57,2305.31 2357.32,2279.57 L7.2@2357.32,2220
  Top Layer w20: C45.1@2733.62,2885 J7.1@3005,2885
  Top Layer w150: v1@2437.95,2312.95 J7.1@3010,2885
  Bottom Layer w150: v1(2437.95,2310) 2437.95,2312.95 J7.1@3010,2885
  other v1: 2437.95,1670 2477.95,1670 2517.95,1670 2557.95,1670 2437.95,1710 2557.95,1710 2437.95,1750 2557.95,1750 2437.95,1790 2557.95,1790 2447.95,1830 2557.95,1830 2447.95,1870 2557.95,1870 2447.95,1910 2557.95,1910 2447.95,1950 2557.95,1950 2447.95,1990 2557.95,1990 2447.95,2030 2557.95,2030 2447.95,2070 2557.95,2070 2447.95,2110 2557.95,2110 2447.95,2150 2557.95,2150 2447.95,2190 2557.95,2190 2447.95,2230 2557.95,2230 2447.95,2270 2557.95,2270 2477.95,2310 2517.95,2310 2557.95,2310
+3.3V: C31.1 C32.1 C33.1 C34.1 C35.1 J5.1 L5.2 R13.2 | length 2708
  Top Layer w10: C31.1@3153.62,2305 3154.49,2305 3179.92,2279.57 L5.2@3179.92,2220
  Top Layer w20: C35.1@3933.62,2885 J5.1@4210,2885
  Top Layer w150: v1(3300.55,2310) 3365.55,2375 3700,2375 J5.1@4210,2885
  Bottom Layer w150: v1(3340.55,2310) v1(3300.55,2310) 3365.55,2375 3700,2375 J5.1@4210,2885
  other v1: 3260.55,1670 3300.55,1670 3340.55,1670 3380.55,1670 3260.55,1710 3380.55,1710 3260.55,1750 3380.55,1750 3260.55,1790 3380.55,1790 3270.55,1830 3380.55,1830 3270.55,1870 3380.55,1870 3270.55,1910 3380.55,1910 3270.55,1950 3380.55,1950 3270.55,1990 3380.55,1990 3270.55,2030 3380.55,2030 3270.55,2070 3380.55,2070 3270.55,2110 3380.55,2110 3270.55,2150 3380.55,2150 3270.55,2190 3380.55,2190 3270.55,2230 3380.55,2230 3270.55,2270 3380.55,2270 3260.55,2310 3380.55,2310
+5V: C8.1 C22.1 C23.1 C24.1 C25.1 J3.1 L2.2 L4.1 L6.1 R3.2 R12.2 | length 3205.6
  Top Layer w7.87: L2.2@1876.14,1999.24 1876.14,2114.99
  Top Layer w10: R3.2@1159.8,2401.14 v2(1210.35,2401.14) ; v2(1420,2370) R12.2@1453.5,2370 ; L6.1@2058.11,1850.79 2058.74,1850.16 2154.33,1850.16 2154.33,1724.17 ; L4.1@2880.71,1850.79 2881.34,1850.16 2936.55,1850.16 2946.39,1860 2976.93,1860 2976.93,1724.17
  Top Layer w20: C8.1@1533.62,2885 J3.1@1810,2885 J3.1@1795,2870
  Signal Layer 2 w10: v2(1210.35,2401.14) 1670,2401.14 1710,2441.14 1810,2441.14 ; v2(1420,2370) 1428.67,2378.67 1753.67,2378.67 1769.5,2394.5 1895.5,2394.5 1943.62,2394.5 v3(1947.13,2391) ; 1888.86,2401.14 1917.9,2401.14 ; 1911.33,2378.67 1934.8,2378.67 1945.17,2389.04 1930,2389.04 ; 1917.9,2181.14 1930,2169.04 ; 1945.17,2169.04 1947.13,2171
  Signal Layer 2 w20: v3(1930,2025) v3(1930,2055)
  Signal Layer 2 w34: v3(1930,1935) v3(1930,1965) v3(1930,1995) v3(1930,2025)
  Signal Layer 2 w100: 1810,2480 1888.86,2401.14 1895.5,2394.5 1911.33,2378.67 1926.95,2363.05 1926.95,2203.05 1930,2200 v3(1930,2185) 1930,2169.04 v3(1930,2150) v3(1930,2055)
  Signal Layer 2 w150: 1810,2480 J3.1@1810,2877.5
AGND1: C19.2 C21.1 NTOS1+.1 U2.20 | length 531.3
  Top Layer w7.87: C21.1@1391.46,2049.76 1406.22,2035 U2.20@1453.46,2035 ; v4(1471.18,1698) NTOS1+.1@1524.06,1698
  Top Layer w10: 1371,2035 U2.20@1451.46,2035
  Signal Layer 2 w7.87: v2(1346.18,1975.75) 1346.18,1821.82 v4@1470.59,1697.41
  other v2: 1346.18,2080.28
  other v4: 1316.16,1974.57 1316.16,2009.8 1346.18,2010.59 1316.16,2045.04 1346.18,2045.43 1316.16,2080.28
B1: C21.2 U2.22 | length 63.9
  Top Layer w7.87: v2(1420,1984.8) 1430.83,1995.63 U2.22@1453.46,1995.63
  Top Layer w10: C21.2@1394.41,1983.82 C21.2@1395.39,1984.8
  Top Layer w19.68: C21.2@1395.39,1984.8 v2(1420,1984.8)
Cb1: R10.1 U2.2 | length 411.6
  Top Layer w7.87: v4(1487.91,1938.81) U2.2@1487.91,1959.8
  Top Layer w10: v2(1700,1775) R10.1@1700,1816.38
  Signal Layer 2 w10: v4(1487.91,1938.81) 1509.18,1917.55 1675.8,1917.55 1700,1893.35 v2(1700,1775)
EN1: R1.1 R2.2 U2.18 | length 474.3
  Top Layer w10: R1.1@1359.96,2399.17 R1.1@1367.83,2399.17 ; v2(1367.83,2357.83) R1.1@1367.83,2399.17 ; v2(1426.89,2158.03) 1426.89,2139.99 1434.76,2132.11 1434.76,2080.28 1439.61,2075.43 U2.18@1452.4,2075.43 ; R2.2@1453.46,2434.17 1403.82,2434.17 1368.82,2399.17 R1.1@1367.83,2399.17
  Signal Layer 2 w10: v2(1367.83,2357.83) 1426.89,2298.78 v2(1426.89,2158.03)
GATEDRIVE: Q1.4 U1.5 | length 74.6
  Top Layer w10: Q1.4@1267.13,965 1296.69,965 1306.69,975 U1.5@1306.69,1005.87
